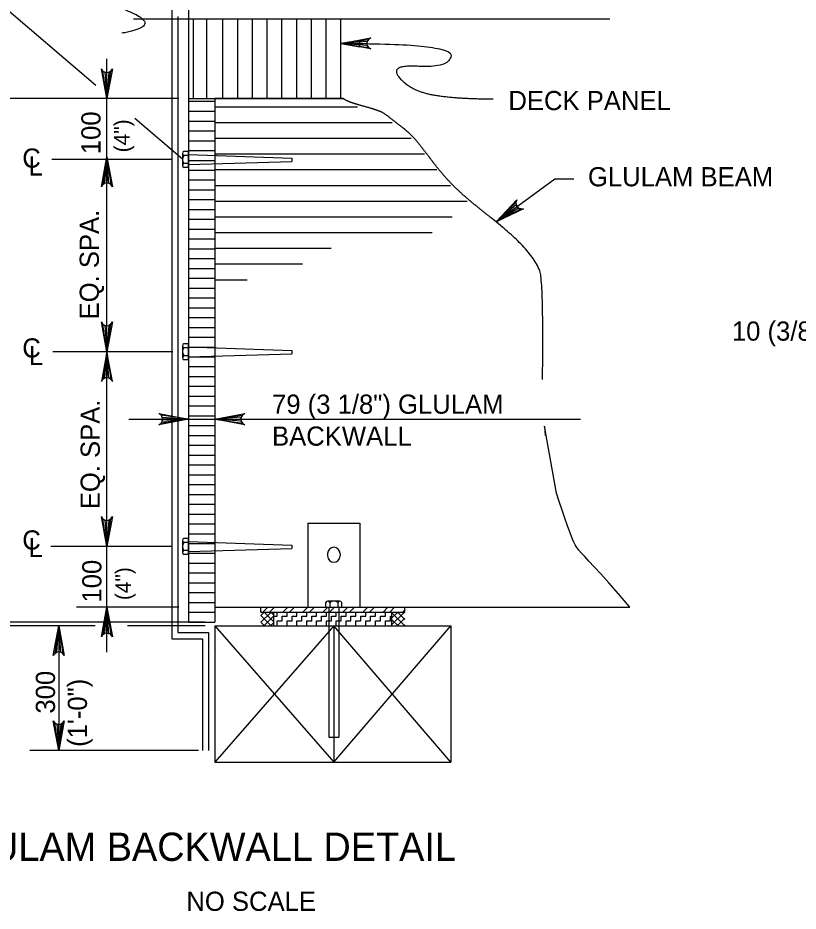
# Model space of a CAD drawing. Extents: x 638263 to 640360, y 293683 to 298655.
# Drawn here: x 639617.3 to 639739.4, y 297622.6 to 297762.5 of the extents above; entities that cross this region are included whole.
import ezdxf

# ---------------------------------------------------------------- set-up
doc = ezdxf.new("R2010")
doc.units = 0
for name, color, linetype in [('3', 7, 'Continuous'), ('5', 7, 'Continuous'), ('7', 7, 'Continuous'), ('8', 7, 'Continuous')]:
    doc.layers.add(name, color=color, linetype=linetype)

msp = doc.modelspace()

# ---------------------------------------------------------------- linework, layer by layer
at = {"layer": '3'}
for p, q in [((639629.53, 297751.9), (639609.93, 297768.6)), ((639631.25, 297740.32), (639631.25, 297756.05)), ((639642.49, 297749.84), (639595.65, 297749.84)), ((639643.09, 297740.36), (639635.63, 297746.71)), ((639641.34, 297740.32), (639622.64, 297740.32)), ((639631.25, 297713.17), (639631.25, 297740.69)), ((639692.16, 297730.52), (639701.36, 297737.27)), ((639701.36, 297737.27), (639704.32, 297737.27)), ((639641.55, 297710.21), (639622.77, 297710.21)), ((639631.25, 297679.74), (639631.25, 297710.21)), ((639634.7, 297699.63), (639705.36, 297699.63)), ((639641.47, 297679.74), (639622.45, 297679.74)), ((639631.25, 297663.18), (639631.25, 297679.74)), ((639642.49, 297670.23), (639626.49, 297670.23)), ((639629.79, 297667.88), (639595.65, 297667.88)), ((639642.49, 297667.88), (639633.92, 297667.88)), ((639623.01, 297667.3), (639619.21, 297667.3)), ((639623.71, 297667.3), (639623.71, 297647.79)), ((639645.56, 297647.79), (639619.21, 297647.79))]:
    msp.add_line(p, q, dxfattribs=at)
for points in [[(639667.87, 297758.47), (639672.53, 297759.34), (639672.17, 297759.09), (639671.98, 297758.78), (639671.93, 297758.47), (639671.98, 297758.16), (639672.17, 297757.84), (639672.53, 297757.6), (639667.87, 297758.47), (639672.17, 297757.84), (639671.98, 297758.16), (639667.87, 297758.47), (639671.93, 297758.47), (639671.98, 297758.78), (639667.87, 297758.47), (639672.17, 297759.09)], [(639631.25, 297749.84), (639630.38, 297754.5), (639630.63, 297754.14), (639630.94, 297753.95), (639631.25, 297753.9), (639631.57, 297753.95), (639631.88, 297754.14), (639632.13, 297754.5), (639631.25, 297749.84), (639631.88, 297754.14), (639631.57, 297753.95), (639631.25, 297749.84), (639631.25, 297753.9), (639630.94, 297753.95), (639631.25, 297749.84), (639630.63, 297754.14)], [(639631.25, 297740.69), (639632.13, 297736.03), (639631.88, 297736.38), (639631.57, 297736.57), (639631.25, 297736.62), (639630.94, 297736.57), (639630.63, 297736.38), (639630.38, 297736.03), (639631.25, 297740.69), (639630.63, 297736.38), (639630.94, 297736.57), (639631.25, 297740.69), (639631.25, 297736.62), (639631.57, 297736.57), (639631.25, 297740.69), (639631.88, 297736.38)], [(639692.16, 297730.52), (639695.4, 297733.98), (639695.26, 297733.57), (639695.29, 297733.21), (639695.43, 297732.92), (639695.66, 297732.7), (639696, 297732.56), (639696.43, 297732.57), (639692.16, 297730.52), (639696, 297732.56), (639695.66, 297732.7), (639692.16, 297730.52), (639695.43, 297732.92), (639695.29, 297733.21), (639692.16, 297730.52), (639695.26, 297733.57)], [(639631.25, 297710.21), (639630.38, 297714.87), (639630.63, 297714.52), (639630.94, 297714.33), (639631.25, 297714.28), (639631.57, 297714.33), (639631.88, 297714.52), (639632.13, 297714.87), (639631.25, 297710.21), (639631.88, 297714.52), (639631.57, 297714.33), (639631.25, 297710.21), (639631.25, 297714.28), (639630.94, 297714.33), (639631.25, 297710.21), (639630.63, 297714.52)], [(639631.25, 297710.21), (639630.38, 297705.55), (639630.63, 297705.91), (639630.94, 297706.1), (639631.25, 297706.15), (639631.57, 297706.1), (639631.88, 297705.91), (639632.13, 297705.55), (639631.25, 297710.21), (639631.88, 297705.91), (639631.57, 297706.1), (639631.25, 297710.21), (639631.25, 297706.15), (639630.94, 297706.1), (639631.25, 297710.21), (639630.63, 297705.91)], [(639644.03, 297699.63), (639639.36, 297698.76), (639639.72, 297699.01), (639639.91, 297699.32), (639639.96, 297699.63), (639639.91, 297699.95), (639639.72, 297700.26), (639639.36, 297700.51), (639644.03, 297699.63), (639639.72, 297700.26), (639639.91, 297699.95), (639644.03, 297699.63), (639639.96, 297699.63), (639639.91, 297699.32), (639644.03, 297699.63), (639639.72, 297699.01)], [(639648.16, 297699.63), (639652.82, 297700.51), (639652.46, 297700.26), (639652.28, 297699.95), (639652.22, 297699.63), (639652.28, 297699.32), (639652.46, 297699.01), (639652.82, 297698.76), (639648.16, 297699.63), (639652.46, 297699.01), (639652.28, 297699.32), (639648.16, 297699.63), (639652.22, 297699.63), (639652.28, 297699.95), (639648.16, 297699.63), (639652.46, 297700.26)], [(639631.25, 297679.74), (639630.38, 297684.4), (639630.63, 297684.04), (639630.94, 297683.86), (639631.25, 297683.8), (639631.57, 297683.86), (639631.88, 297684.04), (639632.13, 297684.4), (639631.25, 297679.74), (639631.88, 297684.04), (639631.57, 297683.86), (639631.25, 297679.74), (639631.25, 297683.8), (639630.94, 297683.86), (639631.25, 297679.74), (639630.63, 297684.04)], [(639631.25, 297670.23), (639632.13, 297665.57), (639631.88, 297665.92), (639631.57, 297666.11), (639631.25, 297666.16), (639630.94, 297666.11), (639630.63, 297665.92), (639630.38, 297665.57), (639631.25, 297670.23), (639630.63, 297665.92), (639630.94, 297666.11), (639631.25, 297670.23), (639631.25, 297666.16), (639631.57, 297666.11), (639631.25, 297670.23), (639631.88, 297665.92)], [(639623.71, 297667.3), (639624.58, 297662.63), (639624.33, 297662.99), (639624.02, 297663.18), (639623.71, 297663.23), (639623.39, 297663.18), (639623.08, 297662.99), (639622.83, 297662.63), (639623.71, 297667.3), (639623.08, 297662.99), (639623.39, 297663.18), (639623.71, 297667.3), (639623.71, 297663.23), (639624.02, 297663.18), (639623.71, 297667.3), (639624.33, 297662.99)], [(639623.71, 297647.79), (639622.83, 297652.45), (639623.08, 297652.1), (639623.39, 297651.91), (639623.71, 297651.86), (639624.02, 297651.91), (639624.33, 297652.1), (639624.58, 297652.45), (639623.71, 297647.79), (639624.33, 297652.1), (639624.02, 297651.91), (639623.71, 297647.79), (639623.71, 297651.86), (639623.39, 297651.91), (639623.71, 297647.79), (639623.08, 297652.1)]]:
    msp.add_lwpolyline(points, dxfattribs=at)
for points in [[(639670.81, 297757.93), (639670.83, 297758.92), (639667.87, 297758.47)], [(639694.84, 297731.87), (639694.25, 297732.67), (639692.16, 297730.52)]]:
    msp.add_lwpolyline(points, close=True, dxfattribs=at)
msp.add_open_spline([(639667.87, 297758.47), (639685.4, 297758.47), (639684.8, 297754.58), (639675.24, 297755.18), (639678.83, 297750.99), (639686, 297749.79), (639691.68, 297749.79)], degree=2, dxfattribs=at)
at = {"layer": '5'}
for p, q in [((639644.03, 297765.87), (639644.03, 297667.88)), ((639641.41, 297763.65), (639641.41, 297665.26)), ((639642.33, 297762.69), (639642.33, 297666.25)), ((639644.79, 297762.25), (639635.43, 297762.25)), ((639709.93, 297762.25), (639644.03, 297762.25)), ((639644.03, 297749.84), (639668.2, 297749.84)), ((639648.16, 297749.84), (639648.16, 297667.88)), ((639643.09, 297741.26), (639643.09, 297739.36)), ((639644.03, 297741.07), (639660.21, 297740.52)), ((639660.21, 297740.52), (639660.21, 297739.97)), ((639644.03, 297739.53), (639660.21, 297739.97)), ((639643.09, 297711.16), (639643.09, 297709.27)), ((639644.03, 297710.97), (639660.21, 297710.42)), ((639644.03, 297709.43), (639660.21, 297709.87)), ((639660.21, 297710.42), (639660.21, 297709.87)), ((639662.67, 297683.35), (639670.83, 297683.35)), ((639662.67, 297683.35), (639662.67, 297670.23)), ((639670.83, 297683.35), (639670.83, 297670.23)), ((639643.09, 297680.68), (639643.09, 297678.78)), ((639644.03, 297680.49), (639660.21, 297679.94)), ((639644.03, 297678.95), (639660.21, 297679.39)), ((639660.21, 297679.94), (639660.21, 297679.39)), ((639665.77, 297678.62), (639665.77, 297678.23)), ((639667.73, 297678.62), (639667.73, 297678.23)), ((639665.5, 297670.23), (639665.5, 297670.94)), ((639667.71, 297671.16), (639665.81, 297671.16)), ((639666.15, 297670.94), (639666.15, 297670.23)), ((639667.39, 297670.94), (639667.39, 297670.23)), ((639668, 297670.23), (639668, 297670.94)), ((639648.16, 297670.23), (639713.09, 297670.23)), ((639655.34, 297670.23), (639677.89, 297670.23)), ((639655.34, 297669.46), (639655.34, 297670.23)), ((639655.34, 297669.46), (639677.89, 297669.46)), ((639655.34, 297667.87), (639656.93, 297669.46)), ((639655.34, 297668.91), (639655.88, 297669.46)), ((639656.97, 297667.3), (639655.34, 297668.93)), ((639655.66, 297669.46), (639656.43, 297670.23)), ((639657.39, 297667.92), (639655.86, 297669.46)), ((639656.7, 297669.46), (639657.48, 297670.23)), ((639657.39, 297668.97), (639656.9, 297669.46)), ((639657.39, 297667.3), (639657.39, 297669.46)), ((639657.91, 297668.83), (639657.91, 297669.46)), ((639658.79, 297669.46), (639659.56, 297670.23)), ((639659.45, 297668.83), (639659.45, 297669.46)), ((639659.84, 297669.46), (639660.61, 297670.23)), ((639660.99, 297668.83), (639660.99, 297669.46)), ((639661.92, 297669.46), (639662.69, 297670.23)), ((639662.52, 297668.83), (639662.52, 297669.46)), ((639662.97, 297669.46), (639663.74, 297670.23)), ((639664.06, 297668.83), (639664.06, 297669.46)), ((639665.06, 297669.46), (639665.83, 297670.23)), ((639665.5, 297670.23), (639668, 297670.23)), ((639665.6, 297668.83), (639665.6, 297669.46)), ((639665.98, 297670.23), (639665.98, 297649.85)), ((639666.1, 297669.46), (639666.87, 297670.23)), ((639667.14, 297668.83), (639667.14, 297669.46)), ((639667.52, 297670.23), (639667.52, 297649.85)), ((639668.19, 297669.46), (639668.96, 297670.23)), ((639668.68, 297668.83), (639668.68, 297669.46)), ((639669.23, 297669.46), (639670, 297670.23)), ((639670.21, 297668.83), (639670.21, 297669.46)), ((639671.32, 297669.46), (639672.09, 297670.23)), ((639671.75, 297668.83), (639671.75, 297669.46)), ((639672.36, 297669.46), (639673.13, 297670.23)), ((639673.29, 297668.83), (639673.29, 297669.46)), ((639674.45, 297669.46), (639675.22, 297670.23)), ((639674.83, 297668.83), (639674.83, 297669.46)), ((639675.5, 297669.46), (639676.26, 297670.23)), ((639675.84, 297668.54), (639676.76, 297669.46)), ((639675.84, 297667.49), (639677.8, 297669.46)), ((639675.84, 297667.3), (639675.84, 297669.46)), ((639677.85, 297667.3), (639675.84, 297669.31)), ((639677.89, 297668.3), (639676.74, 297669.46)), ((639677.58, 297669.46), (639677.89, 297669.76)), ((639677.89, 297669.35), (639677.78, 297669.46)), ((639677.89, 297669.46), (639677.89, 297670.23)), ((639655.93, 297667.3), (639655.34, 297667.88)), ((639655.81, 297667.3), (639657.39, 297668.87)), ((639656.85, 297667.3), (639657.39, 297667.83)), ((639657.39, 297668.83), (639657.91, 297668.83)), ((639657.91, 297668.06), (639658.68, 297668.06)), ((639657.91, 297667.3), (639657.91, 297668.06)), ((639658.68, 297668.83), (639659.45, 297668.83)), ((639658.68, 297668.06), (639658.68, 297668.83)), ((639659.45, 297668.06), (639660.22, 297668.06)), ((639659.45, 297667.3), (639659.45, 297668.06)), ((639660.22, 297668.83), (639660.99, 297668.83)), ((639660.22, 297668.06), (639660.22, 297668.83)), ((639660.99, 297668.06), (639661.75, 297668.06)), ((639660.99, 297667.3), (639660.99, 297668.06)), ((639661.75, 297668.83), (639662.52, 297668.83)), ((639661.75, 297668.06), (639661.75, 297668.83)), ((639662.52, 297668.06), (639663.29, 297668.06)), ((639662.52, 297667.3), (639662.52, 297668.06)), ((639663.29, 297668.83), (639664.06, 297668.83)), ((639663.29, 297668.06), (639663.29, 297668.83)), ((639664.06, 297668.06), (639664.83, 297668.06)), ((639664.06, 297667.3), (639664.06, 297668.06)), ((639664.83, 297668.83), (639665.6, 297668.83)), ((639664.83, 297668.06), (639664.83, 297668.83)), ((639665.6, 297668.06), (639666.37, 297668.06)), ((639665.6, 297667.3), (639665.6, 297668.06)), ((639666.37, 297668.83), (639667.14, 297668.83)), ((639666.37, 297668.06), (639666.37, 297668.83)), ((639667.14, 297668.06), (639667.91, 297668.06)), ((639667.14, 297667.3), (639667.14, 297668.06)), ((639667.91, 297668.83), (639668.68, 297668.83)), ((639667.91, 297668.06), (639667.91, 297668.83)), ((639668.68, 297668.06), (639669.44, 297668.06)), ((639668.68, 297667.3), (639668.68, 297668.06)), ((639669.44, 297668.83), (639670.21, 297668.83)), ((639669.44, 297668.06), (639669.44, 297668.83)), ((639670.21, 297668.06), (639670.98, 297668.06)), ((639670.21, 297667.3), (639670.21, 297668.06)), ((639670.98, 297668.83), (639671.75, 297668.83)), ((639670.98, 297668.06), (639670.98, 297668.83)), ((639671.75, 297668.06), (639672.52, 297668.06)), ((639671.75, 297667.3), (639671.75, 297668.06)), ((639672.52, 297668.83), (639673.29, 297668.83)), ((639672.52, 297668.06), (639672.52, 297668.83)), ((639673.29, 297668.06), (639674.06, 297668.06)), ((639673.29, 297667.3), (639673.29, 297668.06)), ((639674.06, 297668.83), (639674.83, 297668.83)), ((639674.06, 297668.06), (639674.06, 297668.83)), ((639674.83, 297668.06), (639675.6, 297668.06)), ((639674.83, 297667.3), (639674.83, 297668.06)), ((639675.6, 297668.83), (639675.84, 297668.83)), ((639675.6, 297668.06), (639675.6, 297668.83)), ((639676.81, 297667.3), (639675.84, 297668.26)), ((639676.69, 297667.3), (639677.89, 297668.5)), ((639642.33, 297666.25), (639647.13, 297666.25)), ((639647.13, 297666.25), (639647.13, 297647.79)), ((639648.16, 297667.3), (639685.07, 297667.3)), ((639648.16, 297667.3), (639648.16, 297645.95)), ((639648.16, 297667.3), (639666.75, 297645.95)), ((639666.75, 297667.3), (639648.16, 297645.95)), ((639666.75, 297667.3), (639666.75, 297645.95)), ((639666.75, 297645.95), (639685.07, 297667.3)), ((639685.07, 297645.95), (639666.75, 297667.3)), ((639676.18, 297667.29), (639676.18, 297667.29)), ((639677.73, 297667.3), (639677.89, 297667.45)), ((639685.07, 297667.3), (639685.07, 297645.95)), ((639641.41, 297665.26), (639646.2, 297665.26)), ((639646.2, 297665.26), (639646.2, 297647.79)), ((639648.29, 297663.62), (639648.29, 297663.62)), ((639648.26, 297659.21), (639648.26, 297659.21)), ((639666.7, 297659.4), (639666.7, 297659.4)), ((639667.96, 297658.38), (639667.96, 297658.38)), ((639666.08, 297654.93), (639666.08, 297654.93)), ((639666.46, 297652.73), (639666.46, 297652.73)), ((639665.98, 297649.85), (639667.52, 297649.85)), ((639684.87, 297648.52), (639684.87, 297648.52)), ((639648.16, 297645.95), (639685.07, 297645.95)), ((639668.6, 297646.37), (639668.6, 297646.37))]:
    msp.add_line(p, q, dxfattribs=at)
msp.add_lwpolyline([(639668.2, 297749.84), (639667.79, 297749.84), (639648.16, 297749.84), (639648.16, 297685.74)], dxfattribs=at)
for centre, radius, start, end in [((639643.4, 297741.25), 0.316, 107.4518, 252.5482), ((639644.08, 297740.32), 0.994, 141.05, 218.95), ((639643.44, 297739.37), 0.347, 111.2869, 178.1729), ((639643.44, 297739.37), 0.347, 178.1729, 248.7131), ((639643.4, 297711.15), 0.316, 107.4518, 252.5482), ((639644.08, 297710.22), 0.994, 141.05, 218.95), ((639643.44, 297709.28), 0.347, 111.2869, 178.1729), ((639643.44, 297709.28), 0.347, 178.1729, 248.7131), ((639643.4, 297680.67), 0.316, 107.4518, 252.5482), ((639644.08, 297679.74), 0.994, 141.05, 218.95), ((639643.44, 297678.79), 0.347, 111.2869, 178.1729), ((639643.44, 297678.79), 0.347, 178.1729, 248.7131), ((639666.75, 297678.62), 0.976, 0, 180), ((639666.75, 297678.23), 0.976, 180, 0), ((639665.82, 297670.82), 0.347, 88.1729, 158.7131), ((639665.82, 297670.82), 0.347, 21.2869, 88.1729), ((639666.77, 297670.17), 0.994, 51.05, 128.95), ((639667.69, 297670.85), 0.316, 17.4518, 162.5482)]:
    msp.add_arc(centre, radius, start, end, dxfattribs=at)
msp.add_open_spline([(639632.93, 297767.68), (639629.56, 297765.66), (639640.11, 297761.2), (639633.58, 297760.06)], degree=2, dxfattribs=at)
at = {"layer": '7'}
for p, q in [((639644.79, 297749.84), (639644.79, 297762.25)), ((639646.9, 297749.84), (639646.9, 297762.25)), ((639649.41, 297749.84), (639649.41, 297762.25)), ((639651.72, 297749.84), (639651.72, 297762.25)), ((639654.03, 297749.84), (639654.03, 297762.25)), ((639656.33, 297749.84), (639656.33, 297762.25)), ((639658.64, 297749.84), (639658.64, 297762.25)), ((639660.95, 297749.84), (639660.95, 297762.25)), ((639663.25, 297749.84), (639663.25, 297762.25)), ((639665.56, 297749.84), (639665.56, 297762.25)), ((639667.87, 297749.84), (639667.87, 297762.25)), ((639644.03, 297749.84), (639644.03, 297749.84)), ((639644.03, 297749.41), (639648.16, 297749.41)), ((639648.16, 297749.84), (639648.16, 297749.84)), ((639644.03, 297747.85), (639648.16, 297747.85)), ((639648.16, 297748.55), (639670.45, 297748.55)), ((639644.03, 297746.32), (639648.16, 297746.32)), ((639648.17, 297746.09), (639675.91, 297746.09)), ((639644.03, 297744.78), (639648.16, 297744.78)), ((639644.03, 297743.24), (639648.16, 297743.24)), ((639648.17, 297743.63), (639678.86, 297743.63)), ((639644.03, 297741.7), (639648.16, 297741.7)), ((639644.03, 297741.55), (639643.31, 297741.55)), ((639643.31, 297740.95), (639644.03, 297740.95)), ((639644.03, 297739.05), (639644.03, 297741.55)), ((639648.18, 297741.17), (639680.96, 297741.17)), ((639643.31, 297739.7), (639644.03, 297739.7)), ((639644.03, 297739.05), (639643.31, 297739.05)), ((639644.03, 297740.16), (639648.16, 297740.16)), ((639644.03, 297738.63), (639648.16, 297738.63)), ((639648.18, 297738.71), (639682.88, 297738.71)), ((639644.03, 297737.09), (639648.16, 297737.09)), ((639648.19, 297736.24), (639684.99, 297736.24)), ((639644.03, 297735.55), (639648.16, 297735.55)), ((639644.03, 297734.01), (639648.16, 297734.01)), ((639648.19, 297733.78), (639687.61, 297733.78)), ((639644.03, 297732.47), (639648.16, 297732.47)), ((639644.03, 297730.94), (639648.16, 297730.94)), ((639648.2, 297731.32), (639685.27, 297731.32)), ((639644.03, 297729.4), (639648.16, 297729.4)), ((639644.03, 297727.86), (639648.16, 297727.86)), ((639648.2, 297728.86), (639682.12, 297728.86)), ((639644.03, 297726.32), (639648.16, 297726.32)), ((639648.2, 297726.4), (639666.34, 297726.4)), ((639644.03, 297724.78), (639648.16, 297724.78)), ((639648.21, 297723.94), (639661.85, 297723.94)), ((639644.03, 297723.25), (639648.16, 297723.25)), ((639644.03, 297721.71), (639648.16, 297721.71)), ((639648.21, 297721.48), (639653.21, 297721.48)), ((639644.03, 297720.17), (639648.16, 297720.17)), ((639644.03, 297718.63), (639648.16, 297718.63)), ((639644.03, 297717.1), (639648.16, 297717.1)), ((639644.03, 297715.56), (639648.16, 297715.56)), ((639644.03, 297714.02), (639648.16, 297714.02)), ((639644.03, 297712.48), (639648.16, 297712.48)), ((639644.03, 297711.45), (639643.31, 297711.45)), ((639643.31, 297710.85), (639644.03, 297710.85)), ((639644.03, 297708.95), (639644.03, 297711.45)), ((639644.03, 297710.94), (639648.16, 297710.94)), ((639643.31, 297709.6), (639644.03, 297709.6)), ((639644.03, 297708.95), (639643.31, 297708.95)), ((639644.03, 297709.41), (639648.16, 297709.41)), ((639644.03, 297707.87), (639648.16, 297707.87)), ((639644.03, 297706.33), (639648.16, 297706.33)), ((639644.03, 297704.79), (639648.16, 297704.79)), ((639644.03, 297703.25), (639648.16, 297703.25)), ((639644.03, 297701.72), (639648.16, 297701.72)), ((639644.03, 297700.18), (639648.16, 297700.18)), ((639644.03, 297698.64), (639648.16, 297698.64)), ((639644.03, 297697.1), (639648.16, 297697.1)), ((639644.03, 297695.56), (639648.16, 297695.56)), ((639644.03, 297694.03), (639648.16, 297694.03)), ((639644.03, 297692.49), (639648.16, 297692.49)), ((639644.03, 297690.95), (639648.16, 297690.95)), ((639644.03, 297689.41), (639648.16, 297689.41)), ((639644.03, 297687.87), (639648.16, 297687.87)), ((639644.03, 297686.34), (639648.16, 297686.34)), ((639644.03, 297684.8), (639648.16, 297684.8)), ((639644.03, 297683.26), (639648.16, 297683.26)), ((639644.03, 297681.72), (639648.16, 297681.72)), ((639644.03, 297680.97), (639643.31, 297680.97)), ((639643.31, 297680.37), (639644.03, 297680.37)), ((639644.03, 297678.47), (639644.03, 297680.97)), ((639644.03, 297680.19), (639648.16, 297680.19)), ((639643.31, 297679.12), (639644.03, 297679.12)), ((639644.03, 297678.47), (639643.31, 297678.47)), ((639644.03, 297678.65), (639648.16, 297678.65)), ((639644.03, 297677.11), (639648.16, 297677.11)), ((639644.03, 297675.57), (639648.16, 297675.57)), ((639644.03, 297674.03), (639648.16, 297674.03)), ((639644.03, 297672.5), (639648.16, 297672.5)), ((639644.03, 297670.96), (639648.16, 297670.96)), ((639644.03, 297669.42), (639648.16, 297669.42)), ((639644.03, 297667.88), (639648.16, 297667.88))]:
    msp.add_line(p, q, dxfattribs=at)
for points in [[(639701.59, 297688.04), (639699.74, 297698.53), (639699.8, 297697.11)], [(639713.09, 297670.23), (639711.3, 297672.32), (639709.79, 297674.04), (639708.53, 297675.44), (639707.5, 297676.55), (639706.68, 297677.44), (639706.01, 297678.13), (639705.5, 297678.69), (639705.09, 297679.16), (639704.77, 297679.57), (639704.51, 297679.97), (639704.29, 297680.39), (639704.08, 297680.87), (639703.87, 297681.43), (639703.63, 297682.12), (639703.33, 297682.96), (639702.96, 297683.99), (639702.51, 297685.25), (639701.99, 297686.75), (639701.59, 297688.04)]]:
    msp.add_lwpolyline(points, dxfattribs=at)
msp.add_open_spline([(639699.4, 297705.87), (639699.5, 297710.63), (639699.35, 297722.07), (639698.52, 297723.95), (639697.26, 297725.75), (639695.66, 297727.47), (639693.84, 297729.13), (639691.89, 297730.75), (639689.9, 297732.33), (639687.98, 297733.88), (639686.22, 297735.43), (639684.7, 297736.96), (639683.39, 297738.47), (639682.23, 297739.94), (639681.19, 297741.32), (639680.2, 297742.61), (639679.22, 297743.77), (639678.2, 297744.77), (639677.07, 297745.61), (639674.59, 297747.6), (639673.26, 297748.09), (639671.91, 297748.49), (639670.62, 297748.85), (639669.45, 297749.21), (639668.47, 297749.63), (639668.15, 297749.88)], degree=2, dxfattribs=at)
at = {"layer": '8'}
for p, q in [((639646.6, 297667.88), (639595.58, 297667.88)), ((639629.39, 297667.3), (639595.58, 297667.3)), ((639646.6, 297667.3), (639634.45, 297667.3))]:
    msp.add_line(p, q, dxfattribs=at)

# ---------------------------------------------------------------- texts
at = {"layer": '3'}
for s, height, p in [('DECK PANEL', 3, (639694.07, 297748.02)), ('C', 3, (639618.01, 297739.02)), ('L', 3, (639618.99, 297737.79)), ('GLULAM BEAM', 3, (639706.52, 297736.1)), ('10 (3/8") MIN., 20 (13/16") MAX.', 3, (639729.04, 297711.94)), ('C', 3, (639618.01, 297709.3)), ('L', 3, (639619.05, 297708.12)), ('79 (3 1/8") GLULAM', 3, (639657.09, 297700.5)), ('BACKWALL', 3, (639657.09, 297695.5)), ('C', 3, (639618.01, 297679.24)), ('L', 3, (639618.98, 297678.06)), ('GLULAM BACKWALL DETAIL', 4.4292, (639605.22, 297630.5)), ('NO SCALE', 3, (639643.68, 297622.68))]:
    msp.add_text(s, height=height, dxfattribs=at).set_placement(p)
for s, height, p in [('100', 3, (639630.25, 297741.13)), ('(4")', 2.444, (639634.81, 297741.42)), ('EQ. SPA.', 3, (639629.99, 297715.26)), ('EQ. SPA.', 3, (639630.14, 297685.55)), ('100', 3, (639630.39, 297670.94)), ('(4")', 2.444, (639635.03, 297671.32)), ('300', 3, (639623.13, 297653.56)), ('(1\'-0")', 3, (639628.13, 297648.35))]:
    msp.add_text(s, height=height, rotation=90, dxfattribs=at).set_placement(p)

doc.saveas('drawing.dxf')
